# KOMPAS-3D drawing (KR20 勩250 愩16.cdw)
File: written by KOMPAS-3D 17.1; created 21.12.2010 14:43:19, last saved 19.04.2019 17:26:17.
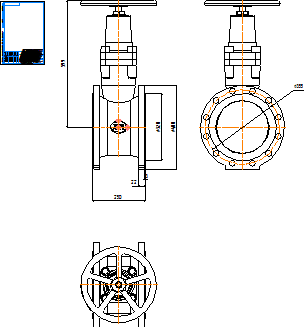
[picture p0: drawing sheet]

Title block, sheet 1: name: KR20 Ду250 Ру16; material: Внимание! Данный продукт является объектом авторского права ООО «Торговый Дом АДЛ». / Запрещается изменение, копирование, распространение / (в том числе путем копирования на другие сайты и ресурсы в Интернете) / или любое иное использование информации и объектов без предварительного / согласия правообладателя (ООО «Торговый Дом АДЛ»).; scale: 1:1; sheets: 1; organisation: ООО "Торговый дом АДЛ"; sheet format: A4; stored path: \\adlc.lan\data\АДЛ_ПКД\3D-модели\ADL production\Клиновые задвижки серии KR ГРАНАР\Клиновые задвижки KR20\KOMPAS 2D\KR20 Ду250 Ру16.cdw

Views: Спереди 1, Проекционный вид 2, Проекционный вид 3
Dimensions and other numbers on the sheet: 3; 22; 250; 320; 400; 599; 355; 1:1; 1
